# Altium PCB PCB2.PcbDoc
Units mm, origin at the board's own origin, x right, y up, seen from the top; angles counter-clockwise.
Board outline 26 x 20 mm, 2 copper layers (Top Layer, Bottom Layer); 2 components, 2 nets, 8 pads, 0 vias.
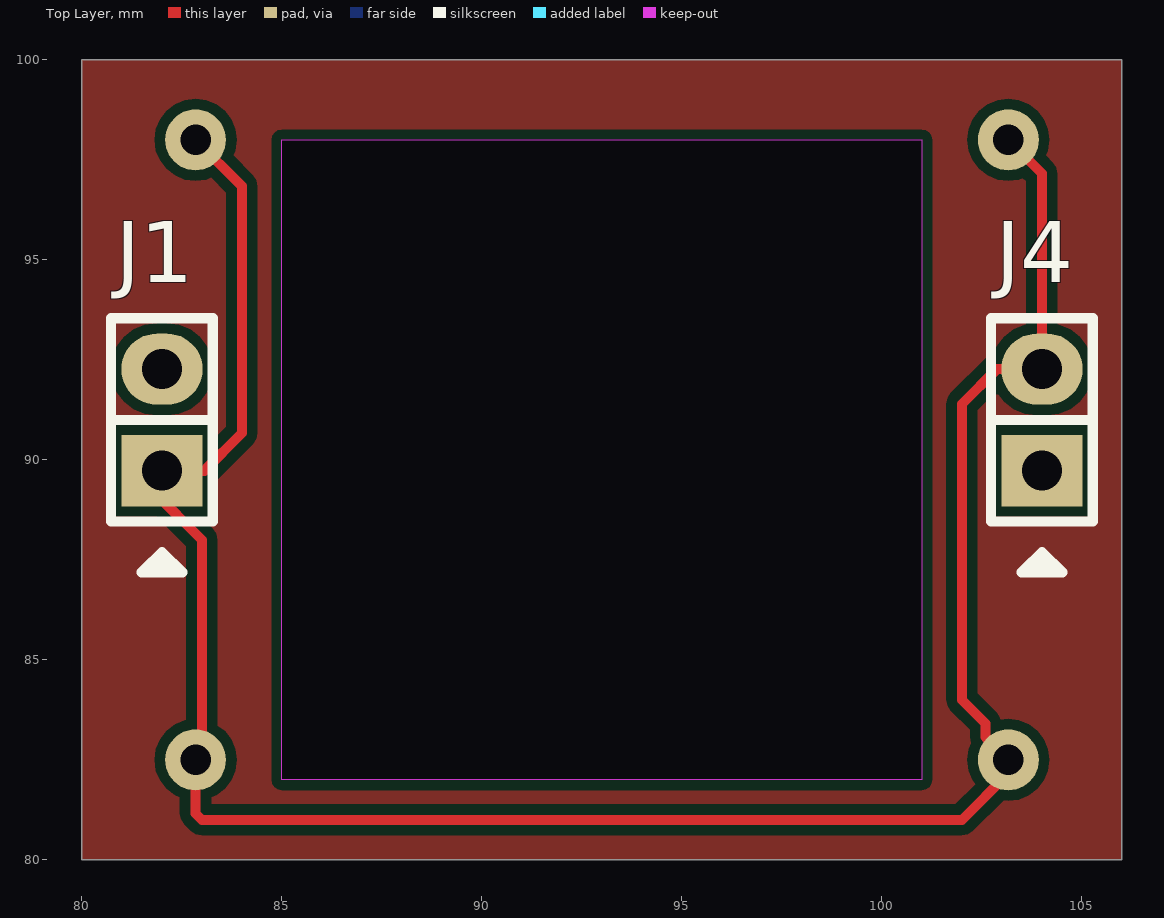
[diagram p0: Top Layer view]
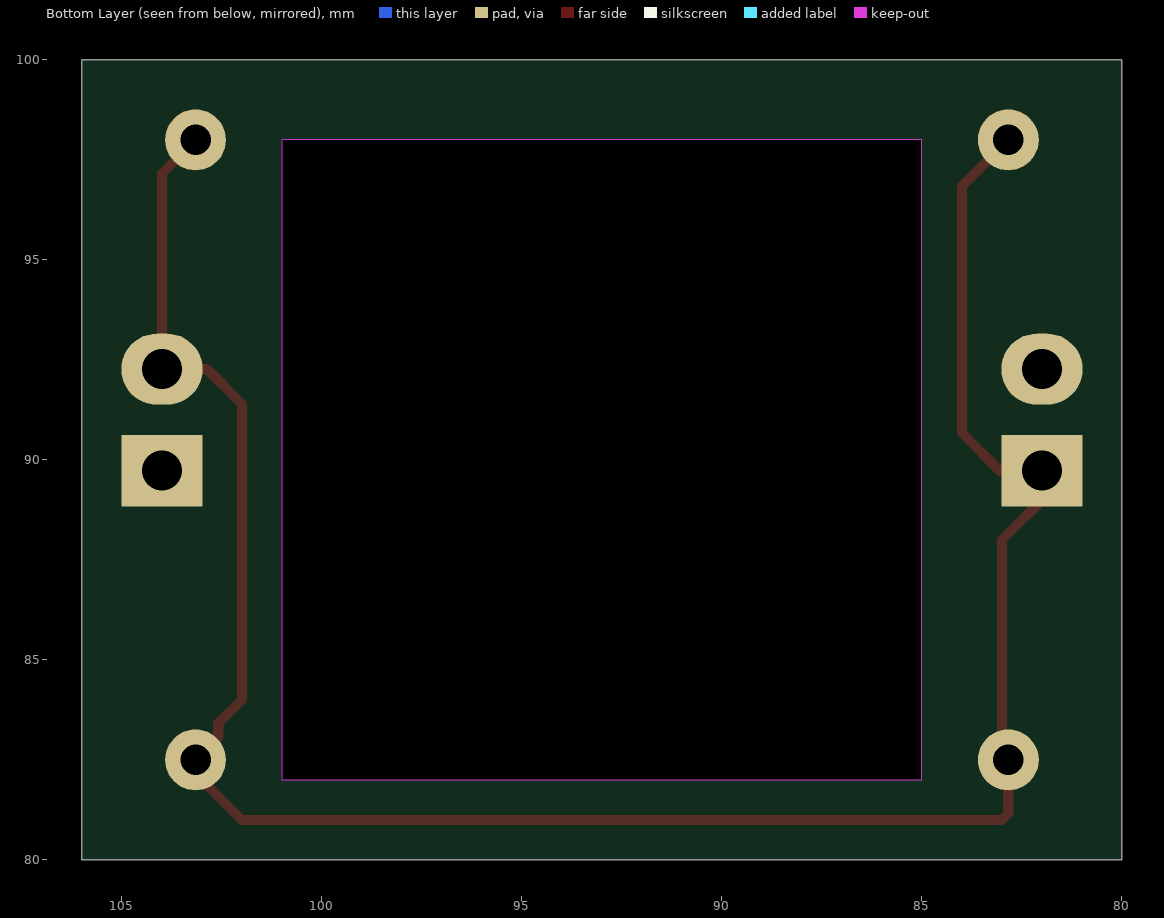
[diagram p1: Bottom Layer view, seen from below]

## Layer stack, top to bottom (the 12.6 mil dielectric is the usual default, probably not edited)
Top Solder: solder mask 0.0102, Solder Resist, Dk 3.5
Top Layer: signal copper 0.0356
Dielectric 1: dielectric 0.32, FR-4, Dk 4.8
Bottom Layer: signal copper 0.0356
Bottom Solder: solder mask 0.0102, Solder Resist, Dk 3.5

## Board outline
80,80 80,100 106,100 106,80
cut-out: 85,98 101,98 101,82 85,82

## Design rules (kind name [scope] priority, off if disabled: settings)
Clearance [All] p1: gap=0.254
PolygonConnect [All] p1: connectstyle=Relief reliefconductorwidth=0.254 reliefentries=4 polygonreliefangle="90 Angle" airgapwidth=0.254
RoutingVias [All] p1: holewidth=0.711 width=1.27 viastyle="Through Hole" minholewidth=0.711 minwidth=1.27 maxholewidth=0.711 maxwidth=1.27
SolderMaskExpansion [All] p1: expansion=0.102
Width [All] p1: maxlimit=0.254 minlimit=0.254 preferedwidth=0.254
29 further rules are at their usual default settings.

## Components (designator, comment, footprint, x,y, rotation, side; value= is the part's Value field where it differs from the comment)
J1 "HDR1x2" PIN-2-2.54-1.0 82,91 r90 top
J4 "HDR1x2" PIN-2-2.54-1.0 104,91 r90 top

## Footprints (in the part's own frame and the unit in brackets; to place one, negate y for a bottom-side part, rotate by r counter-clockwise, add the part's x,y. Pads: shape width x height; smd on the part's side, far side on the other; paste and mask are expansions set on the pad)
PIN-2-2.54-1.0 [mil] "Pin Header"
  rect 70x80 hole 39.37: 1(-50,0)
  oval 70x80 hole 39.37: 2(50,0)
  silkscreen extent -150,-50 100,50, body extent -100,-50 100,50, height 398

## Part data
J1 J4: "Connector"

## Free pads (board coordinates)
  round 1.524 hole 0.762: 0(82.84,98) 1(103.16,98) 2(103.16,82.5) 3(82.84,82.5)

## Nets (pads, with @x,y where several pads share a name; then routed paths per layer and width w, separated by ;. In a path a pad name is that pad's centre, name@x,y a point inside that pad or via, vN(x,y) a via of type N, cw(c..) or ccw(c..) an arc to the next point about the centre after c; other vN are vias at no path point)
A1: J1.1 J4.2 pad.0 pad.1 pad.2 pad.3 | length 57.5
  Top Layer w0.254: J1.1@81.77,89.23 83,88 83,82.66 pad.3 82.84,81.16 83,81 102,81 pad.2@103.16,82.16 ; J1.1 83.058,89.73 84,90.672 84,96.84 pad.0 ; pad.2 102.591,83.069 102.591,83.409 102,84 102,91.4 102.87,92.27 J4.2 104,97.16 pad.1
GND: J1.2
pads on no net: J4.1

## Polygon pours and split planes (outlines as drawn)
no net on Top Layer "Top Layer-No Net" (solid, pour order 2): 106,80 106,100 80,100 80,80 106,80

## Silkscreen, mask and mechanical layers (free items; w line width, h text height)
Mechanical 1:
  lines w0.254: 80,80 80,100 106,100 106,80 80,80 ; 85,82 101,82 101,98 85,98 85,82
